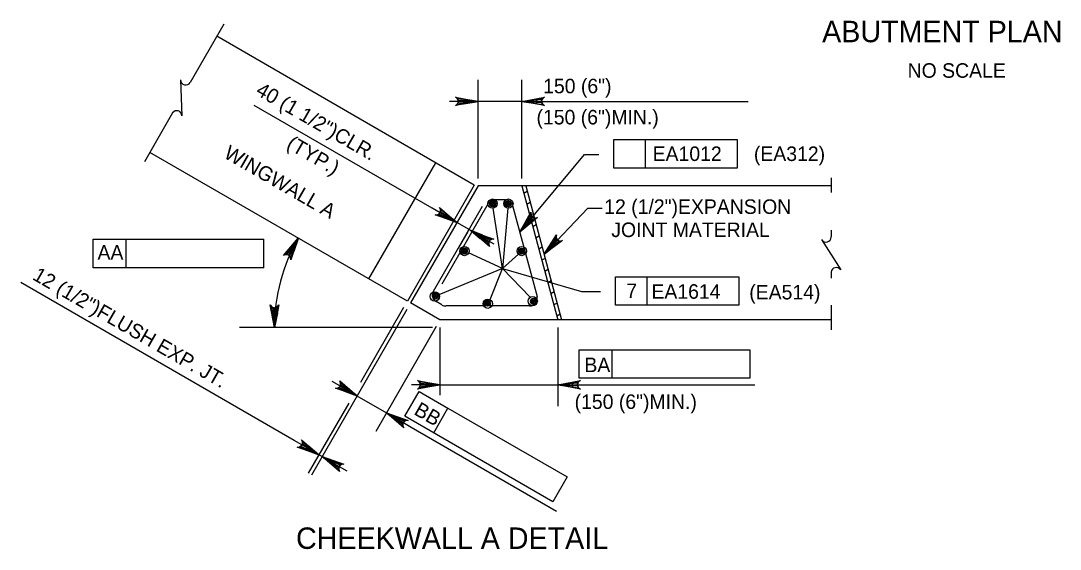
# Model space of a CAD drawing. Extents: x 638340 to 640241, y 295465 to 298435.
# Drawn here: x 638544.3 to 638759.2, y 298122.3 to 298231.5 of the extents above; entities that cross this region are included whole.
import ezdxf

# ---------------------------------------------------------------- set-up
doc = ezdxf.new("R2010")
doc.units = 0
for name, color, linetype in [('10', 7, 'Continuous'), ('3', 7, 'Continuous'), ('4', 7, 'Continuous'), ('5', 7, 'Continuous')]:
    doc.layers.add(name, color=color, linetype=linetype)

msp = doc.modelspace()

# ---------------------------------------------------------------- linework, layer by layer
at = {"layer": '10'}
for p, q in [((638638.04, 298197.57), (638584.81, 298228.3)), ((638624.2, 298173.6), (638570.97, 298204.33)), ((638630.05, 298202.18), (638616.2, 298178.21)), ((638638.04, 298197.57), (638624.2, 298173.6)), ((638638.82, 298197.39), (638624.86, 298173.21)), ((638711.82, 298197.39), (638638.82, 298197.39)), ((638647.88, 298197.39), (638655.3, 298169.7)), ((638648.68, 298197.39), (638656.09, 298169.7)), ((638648.98, 298196.26), (638648.29, 298195.86)), ((638649.6, 298193.95), (638648.91, 298193.55)), ((638650.21, 298191.64), (638649.52, 298191.25)), ((638650.83, 298189.34), (638650.14, 298188.94)), ((638651.45, 298187.03), (638650.76, 298186.63)), ((638652.07, 298184.73), (638651.38, 298184.33)), ((638652.69, 298182.42), (638652, 298182.02)), ((638653.3, 298180.11), (638652.61, 298179.71)), ((638653.92, 298177.8), (638653.23, 298177.4)), ((638654.54, 298175.5), (638653.85, 298175.1)), ((638630.94, 298169.7), (638624.86, 298173.21)), ((638655.16, 298173.19), (638654.47, 298172.79)), ((638711.82, 298169.7), (638630.94, 298169.7)), ((638655.78, 298170.88), (638655.09, 298170.49))]:
    msp.add_line(p, q, dxfattribs=at)
at = {"layer": '3'}
for p, q in [((638638.82, 298198.92), (638638.82, 298219.29)), ((638647.88, 298198.92), (638647.88, 298219.29)), ((638638.82, 298214.86), (638632.92, 298214.86)), ((638647.88, 298214.86), (638638.82, 298214.86)), ((638647.88, 298214.86), (638694.68, 298214.86)), ((638629.34, 298192.77), (638592.53, 298214.01)), ((638666.86, 298206.96), (638692.4, 298206.96)), ((638666.86, 298201.05), (638666.86, 298206.96)), ((638673.45, 298201.05), (638673.45, 298206.96)), ((638692.4, 298206.96), (638692.4, 298201.05)), ((638647.45, 298187.85), (638660.83, 298203.9)), ((638660.83, 298203.9), (638663.78, 298203.9)), ((638692.4, 298201.05), (638666.86, 298201.05)), ((638634.45, 298189.81), (638629.34, 298192.77)), ((638643.85, 298180.33), (638641.94, 298192.78)), ((638644.99, 298192.77), (638643.85, 298180.33)), ((638652.45, 298183.32), (638661.49, 298192.83)), ((638661.49, 298192.83), (638664.44, 298192.83)), ((638634.21, 298189.4), (638632.23, 298185.98)), ((638636.95, 298188.37), (638634.45, 298189.82)), ((638559.23, 298186.38), (638566.08, 298186.38)), ((638559.23, 298180.48), (638559.23, 298186.38)), ((638566.08, 298180.48), (638566.08, 298186.38)), ((638566.08, 298186.38), (638594.53, 298186.38)), ((638594.53, 298180.48), (638594.53, 298186.38)), ((638636.71, 298187.96), (638634.73, 298184.54)), ((638637.61, 298187.99), (638642.06, 298185.42)), ((638643.85, 298180.33), (638636.87, 298183.54)), ((638647.15, 298183.3), (638643.85, 298180.33)), ((638594.53, 298180.48), (638559.23, 298180.48)), ((638643.85, 298180.33), (638630.74, 298174.92)), ((638641.3, 298173.9), (638643.85, 298180.33)), ((638643.85, 298180.33), (638660.18, 298175.58)), ((638649.56, 298174.38), (638643.85, 298180.33)), ((638667.2, 298178.64), (638692.74, 298178.64)), ((638667.2, 298172.73), (638667.2, 298178.64)), ((638673.8, 298172.73), (638673.8, 298178.64)), ((638692.74, 298178.64), (638692.74, 298172.73)), ((638600.81, 298144.8), (638544.29, 298177.44)), ((638660.18, 298175.58), (638664.13, 298175.58)), ((638624.09, 298171.88), (638604.38, 298137.63)), ((638623.43, 298172.26), (638614.49, 298156.75)), ((638692.74, 298172.73), (638667.2, 298172.73)), ((638629.41, 298168.16), (638589.5, 298168.16)), ((638630.17, 298168.37), (638617.65, 298146.68)), ((638630.94, 298168.16), (638630.94, 298154.18)), ((638655.3, 298168.16), (638655.3, 298151.88)), ((638659.7, 298157.64), (638659.7, 298163.55)), ((638659.7, 298163.55), (638666.55, 298163.55)), ((638666.55, 298157.64), (638666.55, 298163.55)), ((638666.55, 298163.55), (638695.01, 298163.55)), ((638695.01, 298163.55), (638695.01, 298157.64)), ((638611.23, 298155.51), (638608.68, 298156.98)), ((638627.99, 298156.31), (638625.04, 298156.31)), ((638630.94, 298156.31), (638655.3, 298156.31)), ((638658.25, 298156.31), (638661.2, 298156.31)), ((638695.01, 298157.64), (638659.7, 298157.64)), ((638661.2, 298156.31), (638696.06, 298156.31)), ((638613.79, 298154.03), (638619.87, 298150.52)), ((638623.71, 298149.8), (638626.66, 298154.92)), ((638626.66, 298154.92), (638632.59, 298151.49)), ((638612.07, 298152.54), (638603.71, 298138.02)), ((638654.28, 298132.15), (638623.71, 298149.8)), ((638629.64, 298146.38), (638632.59, 298151.49)), ((638632.59, 298151.49), (638657.24, 298137.27)), ((638622.42, 298149.04), (638624.98, 298147.57)), ((638624.98, 298147.57), (638655.04, 298130.21)), ((638603.37, 298143.33), (638600.81, 298144.8)), ((638606.59, 298141.47), (638605.93, 298141.85)), ((638609.15, 298139.99), (638611.7, 298138.52)), ((638657.24, 298137.27), (638654.28, 298132.15))]:
    msp.add_line(p, q, dxfattribs=at)
for points in [[(638638.82, 298214.86), (638634.16, 298213.99), (638634.52, 298214.23), (638634.7, 298214.55), (638634.76, 298214.86), (638634.7, 298215.17), (638634.52, 298215.48), (638634.16, 298215.73), (638638.82, 298214.86), (638634.52, 298215.48), (638634.7, 298215.17), (638638.82, 298214.86), (638634.76, 298214.86), (638634.7, 298214.55), (638638.82, 298214.86), (638634.52, 298214.23)], [(638647.88, 298214.86), (638652.54, 298215.73), (638652.18, 298215.48), (638652, 298215.17), (638651.94, 298214.86), (638652, 298214.55), (638652.18, 298214.23), (638652.54, 298213.99), (638647.88, 298214.86), (638652.18, 298214.23), (638652, 298214.55), (638647.88, 298214.86), (638651.94, 298214.86), (638652, 298215.17), (638647.88, 298214.86), (638652.18, 298215.48)], [(638634.45, 298189.81), (638629.97, 298191.39), (638630.41, 298191.43), (638630.73, 298191.6), (638630.93, 298191.85), (638631.04, 298192.14), (638631.04, 298192.51), (638630.85, 298192.9), (638634.45, 298189.81), (638631.04, 298192.51), (638631.04, 298192.14), (638634.45, 298189.81), (638630.93, 298191.85), (638630.73, 298191.6), (638634.45, 298189.81), (638630.41, 298191.43)], [(638647.45, 298187.85), (638649.76, 298191.99), (638649.72, 298191.55), (638649.84, 298191.21), (638650.05, 298190.97), (638650.32, 298190.81), (638650.68, 298190.75), (638651.1, 298190.87), (638647.45, 298187.85), (638650.68, 298190.75), (638650.32, 298190.81), (638647.45, 298187.85), (638650.05, 298190.97), (638649.84, 298191.21), (638647.45, 298187.85), (638649.72, 298191.55)], [(638601.65, 298186.61), (638600.09, 298182.14), (638600.05, 298182.57), (638599.87, 298182.89), (638599.63, 298183.09), (638599.33, 298183.2), (638598.97, 298183.19), (638598.57, 298183.01), (638601.65, 298186.61), (638598.97, 298183.19), (638599.33, 298183.2), (638601.65, 298186.61), (638599.63, 298183.09), (638599.87, 298182.89), (638601.65, 298186.61), (638600.05, 298182.57)], [(638637.61, 298187.99), (638642.09, 298186.42), (638641.65, 298186.38), (638641.34, 298186.2), (638641.13, 298185.96), (638641.02, 298185.66), (638641.03, 298185.3), (638641.21, 298184.9), (638637.61, 298187.99), (638641.03, 298185.3), (638641.02, 298185.66), (638637.61, 298187.99), (638641.13, 298185.96), (638641.34, 298186.2), (638637.61, 298187.99), (638641.65, 298186.38)], [(638652.45, 298183.32), (638655.03, 298187.29), (638654.96, 298186.86), (638655.06, 298186.51), (638655.25, 298186.26), (638655.51, 298186.08), (638655.86, 298186), (638656.29, 298186.09), (638652.45, 298183.32), (638655.86, 298186), (638655.51, 298186.08), (638652.45, 298183.32), (638655.25, 298186.26), (638655.06, 298186.51), (638652.45, 298183.32), (638654.96, 298186.86)], [(638596.73, 298168.16), (638595.85, 298172.83), (638596.1, 298172.47), (638596.42, 298172.28), (638596.73, 298172.23), (638597.04, 298172.28), (638597.35, 298172.47), (638597.6, 298172.83), (638596.73, 298168.16), (638597.35, 298172.47), (638597.04, 298172.28), (638596.73, 298168.16), (638596.73, 298172.23), (638596.42, 298172.28), (638596.73, 298168.16), (638596.1, 298172.47)], [(638613.81, 298154.02), (638609.34, 298155.59), (638609.77, 298155.63), (638610.09, 298155.81), (638610.29, 298156.05), (638610.4, 298156.35), (638610.4, 298156.71), (638610.21, 298157.11), (638613.81, 298154.02), (638610.4, 298156.71), (638610.4, 298156.35), (638613.81, 298154.02), (638610.29, 298156.05), (638610.09, 298155.81), (638613.81, 298154.02), (638609.77, 298155.63)], [(638630.94, 298156.31), (638626.28, 298155.43), (638626.64, 298155.68), (638626.83, 298155.99), (638626.88, 298156.31), (638626.83, 298156.62), (638626.64, 298156.93), (638626.28, 298157.18), (638630.94, 298156.31), (638626.64, 298156.93), (638626.83, 298156.62), (638630.94, 298156.31), (638626.88, 298156.31), (638626.83, 298155.99), (638630.94, 298156.31), (638626.64, 298155.68)], [(638655.3, 298156.31), (638659.96, 298157.18), (638659.6, 298156.93), (638659.42, 298156.62), (638659.36, 298156.31), (638659.42, 298155.99), (638659.6, 298155.68), (638659.96, 298155.43), (638655.3, 298156.31), (638659.6, 298155.68), (638659.42, 298155.99), (638655.3, 298156.31), (638659.36, 298156.31), (638659.42, 298156.62), (638655.3, 298156.31), (638659.6, 298156.93)], [(638619.87, 298150.52), (638624.34, 298148.95), (638623.91, 298148.91), (638623.59, 298148.73), (638623.39, 298148.49), (638623.28, 298148.19), (638623.28, 298147.83), (638623.47, 298147.43), (638619.87, 298150.52), (638623.28, 298147.83), (638623.28, 298148.19), (638619.87, 298150.52), (638623.39, 298148.49), (638623.59, 298148.73), (638619.87, 298150.52), (638623.91, 298148.91)], [(638605.92, 298141.86), (638601.45, 298143.43), (638601.88, 298143.46), (638602.2, 298143.64), (638602.4, 298143.89), (638602.51, 298144.18), (638602.51, 298144.55), (638602.32, 298144.94), (638605.92, 298141.86), (638602.51, 298144.55), (638602.51, 298144.18), (638605.92, 298141.86), (638602.4, 298143.89), (638602.2, 298143.64), (638605.92, 298141.86), (638601.88, 298143.46)], [(638606.6, 298141.46), (638611.08, 298139.89), (638610.64, 298139.85), (638610.32, 298139.68), (638610.12, 298139.43), (638610.01, 298139.13), (638610.01, 298138.77), (638610.2, 298138.38), (638606.6, 298141.46), (638610.01, 298138.77), (638610.01, 298139.13), (638606.6, 298141.46), (638610.12, 298139.43), (638610.32, 298139.68), (638606.6, 298141.46), (638610.64, 298139.85)]]:
    msp.add_lwpolyline(points, dxfattribs=at)
for points in [[(638635.87, 298215.35), (638635.87, 298214.37), (638638.82, 298214.86)], [(638650.83, 298215.35), (638650.83, 298214.37), (638647.88, 298214.86)], [(638632.14, 298191.72), (638631.65, 298190.87), (638634.45, 298189.82)], [(638648.96, 298190.43), (638649.72, 298189.8), (638647.45, 298187.85)], [(638639.75, 298187.32), (638639.26, 298186.47), (638636.95, 298188.37)], [(638600.75, 298183.83), (638599.88, 298184.28), (638601.69, 298186.67)], [(638654.12, 298185.79), (638654.84, 298185.12), (638652.45, 298183.32)], [(638596.35, 298171.14), (638597.34, 298171.1), (638596.73, 298168.16)], [(638627.99, 298156.8), (638627.99, 298155.81), (638630.94, 298156.31)], [(638658.25, 298156.8), (638658.25, 298155.81), (638655.3, 298156.31)], [(638611.48, 298155.93), (638610.99, 298155.08), (638613.79, 298154.03)], [(638622.67, 298149.47), (638622.18, 298148.62), (638619.87, 298150.52)], [(638603.61, 298143.75), (638603.12, 298142.9), (638605.93, 298141.85)], [(638609.39, 298140.42), (638608.9, 298139.57), (638606.59, 298141.47)]]:
    msp.add_lwpolyline(points, close=True, dxfattribs=at)
for centre in [(638641.8, 298193.73), (638645.08, 298193.73), (638635.99, 298183.94), (638647.86, 298183.94), (638629.86, 298174.55), (638640.83, 298173.06), (638650.11, 298173.58)]:
    msp.add_circle(centre, 0.962, dxfattribs=at)
msp.add_arc((638633.74, 298168.16), 37.01, 150.1038, 180, dxfattribs=at)
at = {"layer": '4'}
for p, q in [((638586.24, 298230.78), (638579.31, 298218.79)), ((638577.32, 298219.32), (638577.61, 298211.9)), ((638575.67, 298212.48), (638569.83, 298202.36)), ((638711.82, 298199.03), (638711.82, 298196.02)), ((638709.83, 298186.31), (638713.78, 298180.03)), ((638711.82, 298188.22), (638711.82, 298186.84)), ((638711.82, 298179.56), (638711.82, 298178.32)), ((638711.82, 298172.77), (638711.82, 298167.69))]:
    msp.add_line(p, q, dxfattribs=at)
for centre, start, end in [((638578.39, 298219.32), 180, 330), ((638576.54, 298211.86), 2.1328, 144.6714), ((638710.75, 298186.84), 210, 0), ((638712.88, 298179.46), 32.1328, 174.6714)]:
    msp.add_arc(centre, 1.07, start, end, dxfattribs=at)
at = {"layer": '5'}
for p, q in [((638639.68, 298193.11), (638629.57, 298175.6)), ((638640.93, 298193.73), (638631.32, 298177.08)), ((638644.49, 298194.5), (638642.26, 298194.5)), ((638645.97, 298193.36), (638651.02, 298174.52)), ((638631.36, 298172.79), (638630.13, 298173.5)), ((638649.54, 298172.59), (638632.13, 298172.59))]:
    msp.add_line(p, q, dxfattribs=at)
for centre, radius in [((638641.85, 298193.73), 0.625), ((638641.85, 298193.73), 0.469), ((638641.85, 298193.73), 0.313), ((638641.85, 298193.73), 0.156), ((638645.03, 298193.7), 0.625), ((638645.03, 298193.7), 0.469), ((638645.03, 298193.7), 0.313), ((638645.03, 298193.7), 0.156), ((638635.99, 298183.94), 0.625), ((638635.99, 298183.94), 0.469), ((638635.99, 298183.94), 0.313), ((638635.99, 298183.94), 0.156), ((638647.82, 298183.92), 0.625), ((638647.82, 298183.92), 0.469), ((638647.82, 298183.92), 0.313), ((638647.82, 298183.92), 0.156), ((638630.01, 298174.63), 0.625), ((638630.01, 298174.63), 0.469), ((638630.01, 298174.63), 0.313), ((638630.01, 298174.63), 0.156), ((638640.74, 298173.16), 0.625), ((638640.74, 298173.16), 0.469), ((638640.74, 298173.16), 0.313), ((638640.74, 298173.16), 0.156), ((638650.27, 298173.57), 0.625), ((638650.27, 298173.57), 0.469), ((638650.27, 298173.57), 0.313), ((638650.27, 298173.57), 0.156)]:
    msp.add_circle(centre, radius, dxfattribs=at)
for centre, start, end in [((638642.26, 298192.96), 90, 150), ((638644.49, 298192.96), 15, 90), ((638630.9, 298174.83), 150, 240), ((638649.53, 298174.12), 270, 15), ((638632.13, 298174.12), 240, 270)]:
    msp.add_arc(centre, 1.54, start, end, dxfattribs=at)

# ---------------------------------------------------------------- texts
at = {"layer": '3'}
for s, height, p in [('ABUTMENT PLAN', 4.4294, (638709.95, 298227.08)), ('NO SCALE', 3, (638727.62, 298219.74)), ('150 (6")', 3, (638652.27, 298216.53)), ('(150 (6")MIN.)', 3.0001, (638650.9, 298210.1)), ('EA1012', 3, (638674.91, 298202.54)), ('(EA312)', 3, (638695.84, 298202.54)), ('12 (1/2")EXPANSION', 3.0001, (638664.9, 298191.61)), ('JOINT MATERIAL', 3.0001, (638666.36, 298186.83)), ('AA', 3, (638560.15, 298182.16)), ('7', 3, (638669.46, 298174.22)), ('EA1614', 3, (638674.66, 298174.08)), ('(EA514)', 3, (638694.88, 298173.94)), ('BA', 3, (638660.8, 298158.92)), ('(150 (6")MIN.)', 3.0001, (638658.78, 298151.31)), ('CHEEKWALL A DETAIL', 4.4294, (638601.19, 298122.4))]:
    msp.add_text(s, height=height, dxfattribs=at).set_placement(p)
for s, height, p in [(' 40 (1 1/2")CLR.', 3.0001, (638591.7, 298216.94)), ('WINGWALL A', 3, (638586.03, 298203.35)), ('(TYP.)', 3, (638599.01, 298205.33)), ('12 (1/2")FLUSH EXP. JT.', 3.0001, (638546.51, 298178.18)), ('BB', 3, (638625.36, 298150.31))]:
    msp.add_text(s, height=height, rotation=330, dxfattribs=at).set_placement(p)

doc.saveas('drawing.dxf')
